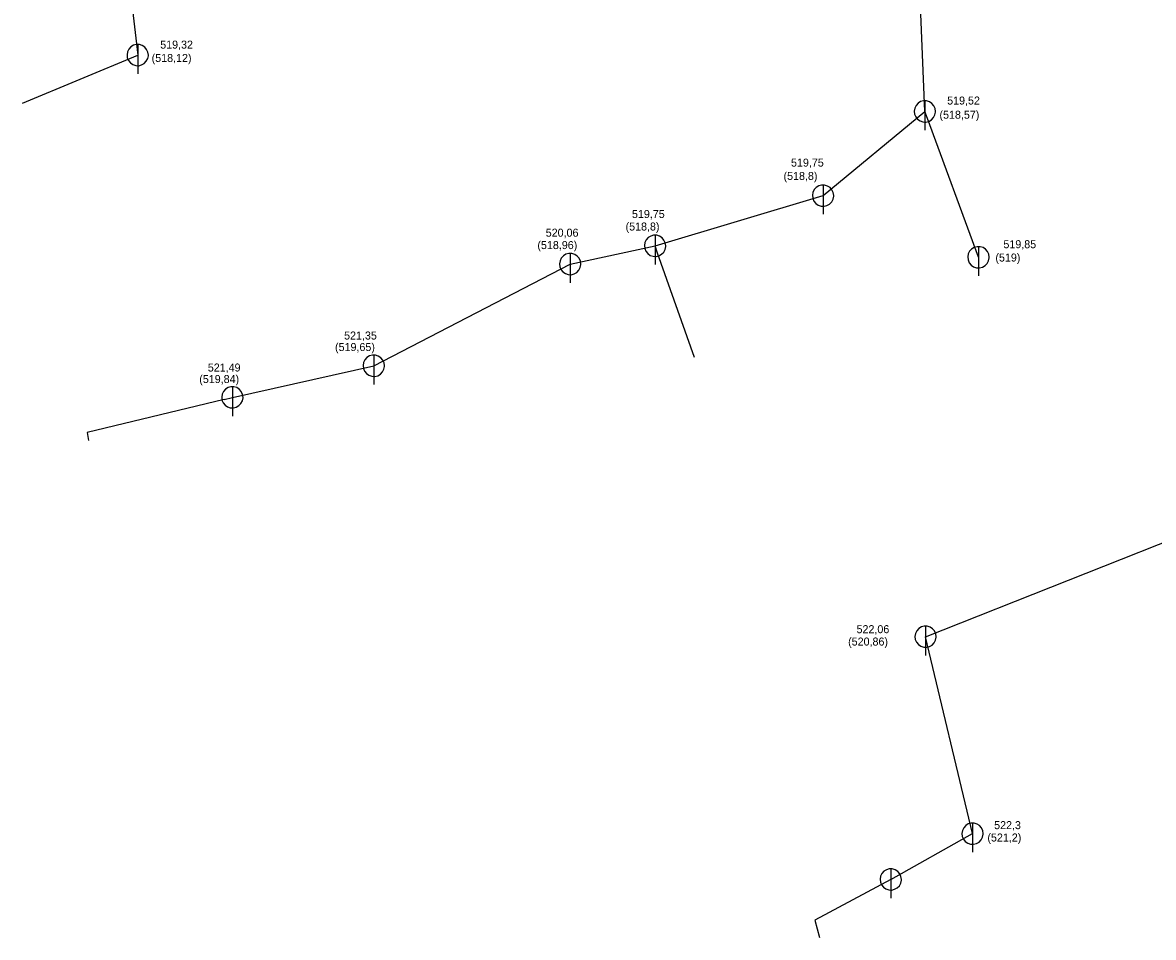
# Model space of a CAD drawing. Extents: x -476058 to -471893, y -1155786 to -1152000.
# Drawn here: x -473989.9 to -473883.9, y -1154074.8 to -1153989 of the extents above; entities that cross this region are included whole.
import ezdxf

# ---------------------------------------------------------------- set-up
doc = ezdxf.new("R2010")
doc.units = 0
for name, color, linetype in [('Vrstva 10', 7, 'Continuous'), ('Vrstva 3', 7, 'Continuous'), ('Vrstva 4', 7, 'Continuous'), ('Vrstva 45', 7, 'Continuous'), ('Vrstva 50', 7, 'Continuous'), ('Vrstva 51', 7, 'Continuous')]:
    doc.layers.add(name, color=color, linetype=linetype)

msp = doc.modelspace()

# ---------------------------------------------------------------- linework, layer by layer
at = {"layer": 'Vrstva 10'}
for p, q in [((-473979.07, -1153991.05), (-473979.07, -1153993.8)), ((-473905.32, -1153996.34), (-473905.32, -1153999.09)), ((-473914.86, -1154004.23), (-473914.86, -1154006.98)), ((-473930.6, -1154008.93), (-473930.6, -1154011.68)), ((-473938.55, -1154010.64), (-473938.55, -1154013.39)), ((-473900.3, -1154010.01), (-473900.3, -1154012.76)), ((-473956.95, -1154020.18), (-473956.95, -1154022.93)), ((-473970.2, -1154023.14), (-473970.2, -1154025.89)), ((-473905.25, -1154045.58), (-473905.25, -1154048.33)), ((-473900.85, -1154064.04), (-473900.85, -1154066.79)), ((-473908.52, -1154068.33), (-473908.52, -1154071.08))]:
    msp.add_line(p, q, dxfattribs=at)
for points in [[(-473978.07, -1153992.05), (-473978.11, -1153991.78), (-473978.23, -1153991.52), (-473978.41, -1153991.3), (-473978.64, -1153991.15), (-473978.91, -1153991.07), (-473979.2, -1153991.06), (-473979.47, -1153991.14), (-473979.71, -1153991.29), (-473979.9, -1153991.5), (-473980.02, -1153991.75), (-473980.07, -1153992.03), (-473980.04, -1153992.31), (-473979.93, -1153992.57), (-473979.75, -1153992.79), (-473979.52, -1153992.95), (-473979.25, -1153993.04), (-473978.97, -1153993.05), (-473978.7, -1153992.98), (-473978.45, -1153992.84), (-473978.26, -1153992.64), (-473978.13, -1153992.39), (-473978.07, -1153992.11), (-473978.07, -1153992.05)], [(-473904.32, -1153997.34), (-473904.35, -1153997.06), (-473904.47, -1153996.8), (-473904.66, -1153996.59), (-473904.89, -1153996.44), (-473905.16, -1153996.35), (-473905.44, -1153996.35), (-473905.72, -1153996.42), (-473905.96, -1153996.57), (-473906.15, -1153996.78), (-473906.27, -1153997.03), (-473906.32, -1153997.31), (-473906.28, -1153997.59), (-473906.17, -1153997.85), (-473906, -1153998.07), (-473905.77, -1153998.23), (-473905.5, -1153998.32), (-473905.22, -1153998.34), (-473904.94, -1153998.27), (-473904.7, -1153998.13), (-473904.5, -1153997.92), (-473904.37, -1153997.67), (-473904.32, -1153997.4), (-473904.32, -1153997.34)], [(-473913.86, -1154005.23), (-473913.9, -1154004.95), (-473914.02, -1154004.7), (-473914.2, -1154004.48), (-473914.44, -1154004.33), (-473914.71, -1154004.24), (-473914.99, -1154004.24), (-473915.26, -1154004.31), (-473915.5, -1154004.46), (-473915.69, -1154004.67), (-473915.81, -1154004.93), (-473915.86, -1154005.2), (-473915.83, -1154005.48), (-473915.72, -1154005.74), (-473915.54, -1154005.96), (-473915.31, -1154006.12), (-473915.04, -1154006.22), (-473914.76, -1154006.23), (-473914.49, -1154006.16), (-473914.24, -1154006.02), (-473914.05, -1154005.81), (-473913.92, -1154005.56), (-473913.86, -1154005.29), (-473913.86, -1154005.23)], [(-473929.6, -1154009.93), (-473929.64, -1154009.66), (-473929.76, -1154009.4), (-473929.94, -1154009.18), (-473930.17, -1154009.03), (-473930.44, -1154008.95), (-473930.73, -1154008.94), (-473931, -1154009.02), (-473931.24, -1154009.17), (-473931.43, -1154009.37), (-473931.55, -1154009.63), (-473931.6, -1154009.91), (-473931.57, -1154010.19), (-473931.46, -1154010.45), (-473931.28, -1154010.67), (-473931.05, -1154010.83), (-473930.78, -1154010.92), (-473930.5, -1154010.93), (-473930.23, -1154010.86), (-473929.98, -1154010.72), (-473929.79, -1154010.52), (-473929.66, -1154010.27), (-473929.6, -1154009.99), (-473929.6, -1154009.93)], [(-473937.55, -1154011.64), (-473937.59, -1154011.36), (-473937.71, -1154011.1), (-473937.89, -1154010.89), (-473938.12, -1154010.74), (-473938.4, -1154010.65), (-473938.68, -1154010.65), (-473938.95, -1154010.72), (-473939.19, -1154010.87), (-473939.38, -1154011.08), (-473939.5, -1154011.33), (-473939.55, -1154011.61), (-473939.52, -1154011.89), (-473939.41, -1154012.15), (-473939.23, -1154012.37), (-473939, -1154012.53), (-473938.73, -1154012.62), (-473938.45, -1154012.64), (-473938.18, -1154012.57), (-473937.93, -1154012.43), (-473937.74, -1154012.22), (-473937.61, -1154011.97), (-473937.55, -1154011.7), (-473937.55, -1154011.64)], [(-473899.3, -1154011.01), (-473899.34, -1154010.73), (-473899.46, -1154010.47), (-473899.64, -1154010.26), (-473899.87, -1154010.1), (-473900.14, -1154010.02), (-473900.43, -1154010.02), (-473900.7, -1154010.09), (-473900.94, -1154010.24), (-473901.13, -1154010.45), (-473901.25, -1154010.7), (-473901.3, -1154010.98), (-473901.27, -1154011.26), (-473901.16, -1154011.52), (-473900.98, -1154011.74), (-473900.75, -1154011.9), (-473900.48, -1154011.99), (-473900.2, -1154012), (-473899.92, -1154011.94), (-473899.68, -1154011.79), (-473899.49, -1154011.59), (-473899.36, -1154011.34), (-473899.3, -1154011.06), (-473899.3, -1154011.01)], [(-473955.95, -1154021.18), (-473955.99, -1154020.9), (-473956.11, -1154020.64), (-473956.29, -1154020.43), (-473956.53, -1154020.27), (-473956.8, -1154020.19), (-473957.08, -1154020.19), (-473957.35, -1154020.26), (-473957.59, -1154020.41), (-473957.78, -1154020.62), (-473957.9, -1154020.87), (-473957.95, -1154021.15), (-473957.92, -1154021.43), (-473957.81, -1154021.69), (-473957.63, -1154021.91), (-473957.4, -1154022.07), (-473957.13, -1154022.16), (-473956.85, -1154022.18), (-473956.58, -1154022.11), (-473956.33, -1154021.97), (-473956.14, -1154021.76), (-473956.01, -1154021.51), (-473955.95, -1154021.24), (-473955.95, -1154021.18)], [(-473969.2, -1154024.14), (-473969.24, -1154023.86), (-473969.36, -1154023.6), (-473969.54, -1154023.39), (-473969.78, -1154023.23), (-473970.05, -1154023.15), (-473970.33, -1154023.15), (-473970.6, -1154023.22), (-473970.84, -1154023.37), (-473971.03, -1154023.58), (-473971.16, -1154023.83), (-473971.2, -1154024.11), (-473971.17, -1154024.39), (-473971.06, -1154024.65), (-473970.88, -1154024.87), (-473970.65, -1154025.03), (-473970.39, -1154025.12), (-473970.1, -1154025.13), (-473969.83, -1154025.06), (-473969.59, -1154024.92), (-473969.39, -1154024.72), (-473969.26, -1154024.47), (-473969.2, -1154024.19), (-473969.2, -1154024.14)], [(-473904.25, -1154046.58), (-473904.29, -1154046.3), (-473904.41, -1154046.04), (-473904.59, -1154045.83), (-473904.82, -1154045.67), (-473905.09, -1154045.59), (-473905.38, -1154045.59), (-473905.65, -1154045.66), (-473905.89, -1154045.81), (-473906.08, -1154046.02), (-473906.2, -1154046.27), (-473906.25, -1154046.55), (-473906.22, -1154046.83), (-473906.11, -1154047.09), (-473905.93, -1154047.31), (-473905.7, -1154047.47), (-473905.43, -1154047.56), (-473905.15, -1154047.57), (-473904.88, -1154047.51), (-473904.63, -1154047.36), (-473904.44, -1154047.16), (-473904.31, -1154046.91), (-473904.25, -1154046.63), (-473904.25, -1154046.58)], [(-473899.85, -1154065.04), (-473899.89, -1154064.77), (-473900.01, -1154064.51), (-473900.19, -1154064.29), (-473900.42, -1154064.14), (-473900.7, -1154064.06), (-473900.98, -1154064.05), (-473901.25, -1154064.13), (-473901.49, -1154064.28), (-473901.68, -1154064.49), (-473901.8, -1154064.74), (-473901.85, -1154065.02), (-473901.82, -1154065.3), (-473901.71, -1154065.56), (-473901.53, -1154065.78), (-473901.3, -1154065.94), (-473901.03, -1154066.03), (-473900.75, -1154066.04), (-473900.48, -1154065.97), (-473900.23, -1154065.83), (-473900.04, -1154065.63), (-473899.91, -1154065.38), (-473899.85, -1154065.1), (-473899.85, -1154065.04)], [(-473907.52, -1154069.33), (-473907.56, -1154069.05), (-473907.68, -1154068.8), (-473907.86, -1154068.58), (-473908.1, -1154068.43), (-473908.37, -1154068.34), (-473908.65, -1154068.34), (-473908.92, -1154068.42), (-473909.16, -1154068.56), (-473909.35, -1154068.77), (-473909.48, -1154069.03), (-473909.52, -1154069.3), (-473909.49, -1154069.58), (-473909.38, -1154069.84), (-473909.2, -1154070.06), (-473908.97, -1154070.23), (-473908.71, -1154070.32), (-473908.42, -1154070.33), (-473908.15, -1154070.26), (-473907.91, -1154070.12), (-473907.71, -1154069.92), (-473907.58, -1154069.67), (-473907.52, -1154069.39), (-473907.52, -1154069.33)]]:
    msp.add_lwpolyline(points, dxfattribs=at)
at = {"layer": 'Vrstva 45'}
for points in [[(-473905.32, -1153997.34), (-473905.84, -1153984.35)], [(-473914.86, -1154005.23), (-473905.32, -1153997.34)], [(-473930.6, -1154009.93), (-473914.86, -1154005.23)], [(-473938.55, -1154011.64), (-473930.6, -1154009.93)], [(-473956.95, -1154021.18), (-473938.55, -1154011.64)], [(-473970.2, -1154024.14), (-473956.95, -1154021.18)]]:
    msp.add_lwpolyline(points, dxfattribs=at)
at = {"layer": 'Vrstva 50'}
for points in [[(-473981.26, -1153973.16), (-473979.07, -1153992.05)], [(-473900.3, -1154011.01), (-473905.07, -1153998.01), (-473905.32, -1153997.34)], [(-473905.25, -1154046.58), (-473878.46, -1154035.96)], [(-473908.52, -1154069.33), (-473900.85, -1154065.04), (-473905.25, -1154046.58)]]:
    msp.add_lwpolyline(points, dxfattribs=at)
at = {"layer": 'Vrstva 51'}
for points in [[(-473989.85, -1153996.55), (-473979.07, -1153992.05)], [(-473926.9, -1154020.4), (-473930.36, -1154010.62), (-473930.6, -1154009.93)], [(-473970.98, -1154024.33), (-473983.79, -1154027.44), (-473983.69, -1154028.19)], [(-473970.98, -1154024.33), (-473970.2, -1154024.14)], [(-473908.52, -1154069.33), (-473915.63, -1154073.16), (-473915.19, -1154074.77)]]:
    msp.add_lwpolyline(points, dxfattribs=at)

# ---------------------------------------------------------------- texts
at = {"layer": 'Vrstva 3'}
for s, p in [('519,32', (-473976.96, -1153991.45)), ('519,52', (-473903.23, -1153996.69)), ('519,75', (-473917.86, -1154002.51)), ('519,75', (-473932.76, -1154007.33)), ('520,06', (-473940.84, -1154009.08)), ('519,85', (-473897.96, -1154010.16)), ('521,35', (-473959.73, -1154018.72)), ('521,49', (-473972.5, -1154021.72)), ('522,06', (-473911.72, -1154046.25)), ('522,3', (-473898.83, -1154064.62))]:
    msp.add_text(s, height=0.75, dxfattribs=at).set_placement(p)
at = {"layer": 'Vrstva 4'}
for s, p in [('(518,12)', (-473977.76, -1153992.7)), ('(518,57)', (-473903.95, -1153998.02)), ('(518,8)', (-473918.56, -1154003.76)), ('(518,8)', (-473933.36, -1154008.5)), ('(518,96)', (-473941.62, -1154010.24)), ('(519)', (-473898.71, -1154011.41)), ('(519,65)', (-473960.58, -1154019.8)), ('(519,84)', (-473973.3, -1154022.8)), ('(520,86)', (-473912.51, -1154047.41)), ('(521,2)', (-473899.46, -1154065.78))]:
    msp.add_text(s, height=0.75, dxfattribs=at).set_placement(p)

doc.saveas('drawing.dxf')
